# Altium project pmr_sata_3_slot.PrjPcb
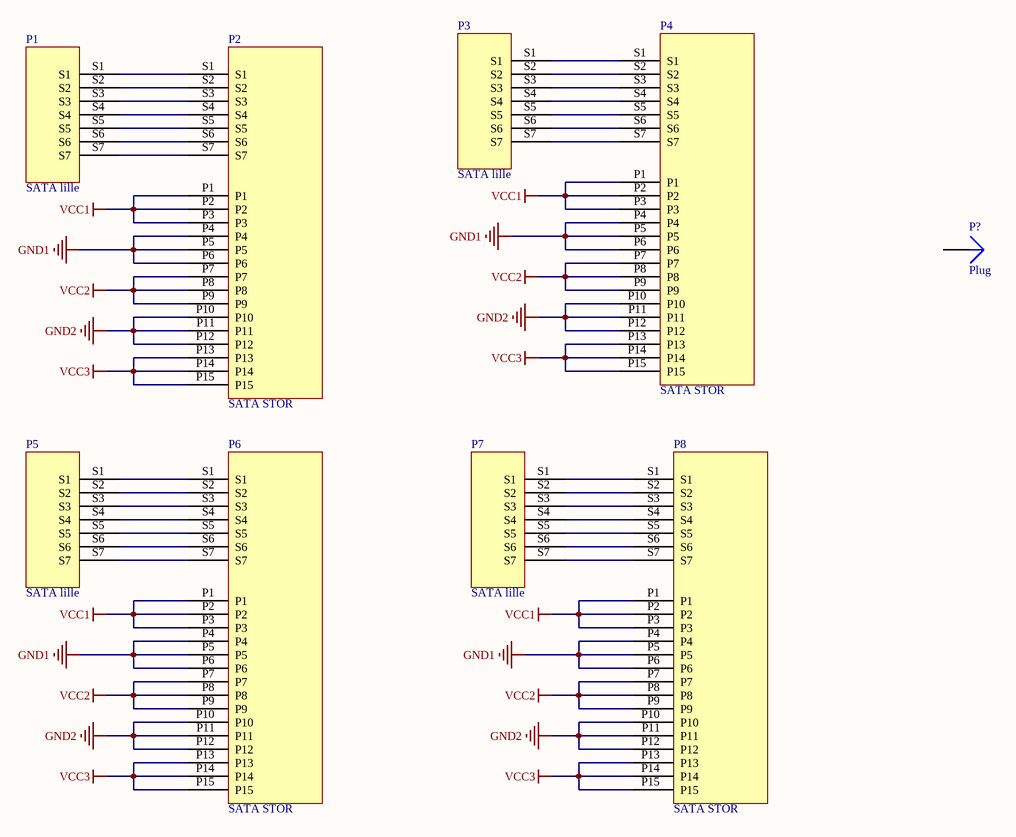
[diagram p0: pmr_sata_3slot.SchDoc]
2 sheets, 11 parts. Net scope: flat (ports and power ports of the same name join across sheets).
Board file: pmr_sata7_3slot.PcbDoc
Sheets:
  pmr_sata_3slot.SchDoc
  pmr_sata_single_3slot.SchDoc

## Sheet pmr_sata_3slot.SchDoc
size A4

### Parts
(Parts that share a designator on the sheet are numbered #1, #2 ... from top to bottom, then left to right.)
P1#1  SATA lille  [pmr_sata -lille]
P2#1  SATA STOR  [pmr_sata]
P3  SATA lille  [pmr_sata -lille]
P4  SATA STOR  [pmr_sata]
P5  SATA lille  [pmr_sata -lille]
P6  SATA STOR  [pmr_sata]
P7  SATA lille  [pmr_sata -lille]
P8  SATA STOR  [pmr_sata]
P?  Plug  [PIN1]

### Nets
GND1: P2#1.P4 P2#1.P5 P2#1.P6 P4.P4 P4.P5 P4.P6 P6.P4 P6.P5 P6.P6 P8.P4 P8.P5 P8.P6
GND2: P2#1.P10 P2#1.P11 P2#1.P12 P4.P10 P4.P11 P4.P12 P6.P10 P6.P11 P6.P12 P8.P10 P8.P11 P8.P12
VCC1: P2#1.P1 P2#1.P2 P2#1.P3 P4.P1 P4.P2 P4.P3 P6.P1 P6.P2 P6.P3 P8.P1 P8.P2 P8.P3
VCC2: P2#1.P7 P2#1.P8 P2#1.P9 P4.P7 P4.P8 P4.P9 P6.P7 P6.P8 P6.P9 P8.P7 P8.P8 P8.P9
VCC3: P2#1.P13 P2#1.P14 P2#1.P15 P4.P13 P4.P14 P4.P15 P6.P13 P6.P14 P6.P15 P8.P13 P8.P14 P8.P15
NetP1#1_S1: P1#1.S1 P2#1.S1
NetP1#1_S2: P1#1.S2 P2#1.S2
NetP1#1_S3: P1#1.S3 P2#1.S3
NetP1#1_S4: P1#1.S4 P2#1.S4
NetP1#1_S5: P1#1.S5 P2#1.S5
NetP1#1_S6: P1#1.S6 P2#1.S6
NetP1#1_S7: P1#1.S7 P2#1.S7
NetP3_S1: P3.S1 P4.S1
NetP3_S2: P3.S2 P4.S2
NetP3_S3: P3.S3 P4.S3
NetP3_S4: P3.S4 P4.S4
NetP3_S5: P3.S5 P4.S5
NetP3_S6: P3.S6 P4.S6
NetP3_S7: P3.S7 P4.S7
NetP5_S1: P5.S1 P6.S1
NetP5_S2: P5.S2 P6.S2
NetP5_S3: P5.S3 P6.S3
NetP5_S4: P5.S4 P6.S4
NetP5_S5: P5.S5 P6.S5
NetP5_S6: P5.S6 P6.S6
NetP5_S7: P5.S7 P6.S7
NetP7_S1: P7.S1 P8.S1
NetP7_S2: P7.S2 P8.S2
NetP7_S3: P7.S3 P8.S3
NetP7_S4: P7.S4 P8.S4
NetP7_S5: P7.S5 P8.S5
NetP7_S6: P7.S6 P8.S6
NetP7_S7: P7.S7 P8.S7

Not connected (* = marked no-connect by the designer): P? 1

## Sheet pmr_sata_single_3slot.SchDoc
size A4
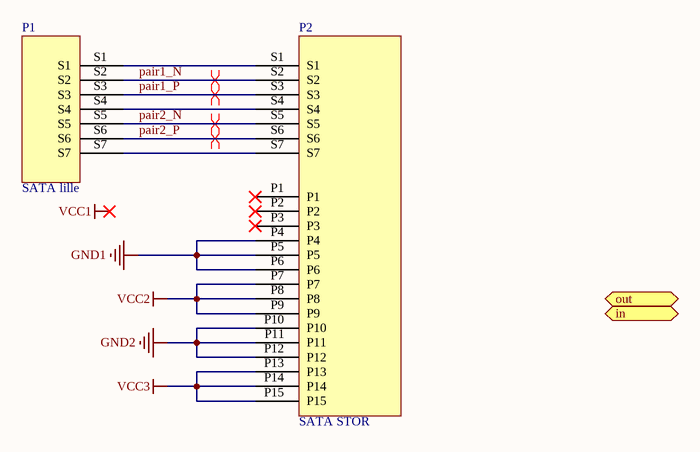
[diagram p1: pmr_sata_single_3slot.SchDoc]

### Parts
(Parts that share a designator on the sheet are numbered #1, #2 ... from top to bottom, then left to right.)
P1#2  SATA lille  [pmr_sata -lille ny]
P2#2  SATA STOR  [pmr_sata]

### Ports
in (in), out (out)

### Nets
GND1: P2#2.P4 P2#2.P5 P2#2.P6
GND2: P2#2.P10 P2#2.P11 P2#2.P12
VCC2: P2#2.P7 P2#2.P8 P2#2.P9
VCC3: P2#2.P13 P2#2.P14 P2#2.P15
pair1_N: P1#2.S2 P2#2.S2
pair1_P: P1#2.S3 P2#2.S3
pair2_N: P1#2.S5 P2#2.S5
pair2_P: P1#2.S6 P2#2.S6
NetP1#2_S1: P1#2.S1 P2#2.S1
NetP1#2_S4: P1#2.S4 P2#2.S4
NetP1#2_S7: P1#2.S7 P2#2.S7

Not connected (* = marked no-connect by the designer): P2#2 P1* P2* P3*

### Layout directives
differential pair: pair1_N, pair1_P, pair2_N, pair2_P

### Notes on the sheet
- Labels drawn without touching a wire or pin: VCC1

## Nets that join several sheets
GND1: pmr_sata_3slot (12 pins), pmr_sata_single_3slot (P2#2.P4 P2#2.P5 P2#2.P6)
GND2: pmr_sata_3slot (12 pins), pmr_sata_single_3slot (P2#2.P10 P2#2.P11 P2#2.P12)
VCC2: pmr_sata_3slot (12 pins), pmr_sata_single_3slot (P2#2.P7 P2#2.P8 P2#2.P9)
VCC3: pmr_sata_3slot (12 pins), pmr_sata_single_3slot (P2#2.P13 P2#2.P14 P2#2.P15)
